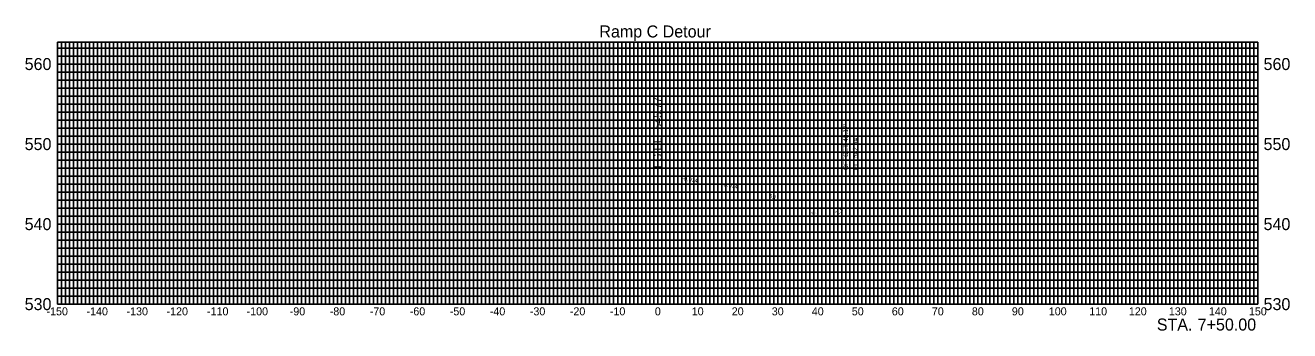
# Model space of a CAD drawing. Extents: x -158 to 158, y 523 to 600.
import ezdxf

# ---------------------------------------------------------------- set-up
doc = ezdxf.new("R2010")
doc.units = 0
for name, color, linetype in [('DES - SHEET - Light Grid', 7, 'Continuous'), ('DES - SHEET - Linework', 7, 'Continuous'), ('DES - XS - Proposed - Finished Grade Slopes Text', 7, 'Continuous'), ('DES - XS - Proposed - Text', 7, 'Continuous')]:
    doc.layers.add(name, color=color, linetype=linetype)

msp = doc.modelspace()

# ---------------------------------------------------------------- linework, layer by layer
at = {"layer": 'DES - SHEET - Light Grid'}
for p, q in [((-149, 530), (-149, 595.44)), ((-148, 530), (-148, 595.44)), ((-147, 530), (-147, 595.44)), ((-146, 530), (-146, 595.44)), ((-145, 530), (-145, 595.44)), ((-144, 530), (-144, 595.44)), ((-143, 530), (-143, 595.44)), ((-142, 530), (-142, 595.44)), ((-141, 530), (-141, 595.44)), ((-139, 530), (-139, 595.44)), ((-138, 530), (-138, 595.44)), ((-137, 530), (-137, 595.44)), ((-136, 530), (-136, 595.44)), ((-135, 530), (-135, 595.44)), ((-134, 530), (-134, 595.44)), ((-133, 530), (-133, 595.44)), ((-132, 530), (-132, 595.44)), ((-131, 530), (-131, 595.44)), ((-129, 530), (-129, 595.44)), ((-128, 530), (-128, 595.44)), ((-127, 530), (-127, 595.44)), ((-126, 530), (-126, 595.44)), ((-125, 530), (-125, 595.44)), ((-124, 530), (-124, 595.44)), ((-123, 530), (-123, 595.44)), ((-122, 530), (-122, 595.44)), ((-121, 530), (-121, 595.44)), ((-119, 530), (-119, 595.44)), ((-118, 530), (-118, 595.44)), ((-117, 530), (-117, 595.44)), ((-116, 530), (-116, 595.44)), ((-115, 530), (-115, 595.44)), ((-114, 530), (-114, 595.44)), ((-113, 530), (-113, 595.44)), ((-112, 530), (-112, 595.44)), ((-111, 530), (-111, 595.44)), ((-109, 530), (-109, 595.44)), ((-108, 530), (-108, 595.44)), ((-107, 530), (-107, 595.44)), ((-106, 530), (-106, 595.44)), ((-105, 530), (-105, 595.44)), ((-104, 530), (-104, 595.44)), ((-103, 530), (-103, 595.44)), ((-102, 530), (-102, 595.44)), ((-101, 530), (-101, 595.44)), ((-99, 530), (-99, 595.44)), ((-98, 530), (-98, 595.44)), ((-97, 530), (-97, 595.44)), ((-96, 530), (-96, 595.44)), ((-95, 530), (-95, 595.44)), ((-94, 530), (-94, 595.44)), ((-93, 530), (-93, 595.44)), ((-92, 530), (-92, 595.44)), ((-91, 530), (-91, 595.44)), ((-89, 530), (-89, 595.44)), ((-88, 530), (-88, 595.44)), ((-87, 530), (-87, 595.44)), ((-86, 530), (-86, 595.44)), ((-85, 530), (-85, 595.44)), ((-84, 530), (-84, 595.44)), ((-83, 530), (-83, 595.44)), ((-82, 530), (-82, 595.44)), ((-81, 530), (-81, 595.44)), ((-79, 530), (-79, 595.44)), ((-78, 530), (-78, 595.44)), ((-77, 530), (-77, 595.44)), ((-76, 530), (-76, 595.44)), ((-75, 530), (-75, 595.44)), ((-74, 530), (-74, 595.44)), ((-73, 530), (-73, 595.44)), ((-72, 530), (-72, 595.44)), ((-71, 530), (-71, 595.44)), ((-69, 530), (-69, 595.44)), ((-68, 530), (-68, 595.44)), ((-67, 530), (-67, 595.44)), ((-66, 530), (-66, 595.44)), ((-65, 530), (-65, 595.44)), ((-64, 530), (-64, 595.44)), ((-63, 530), (-63, 595.44)), ((-62, 530), (-62, 595.44)), ((-61, 530), (-61, 595.44)), ((-59, 530), (-59, 595.44)), ((-58, 530), (-58, 595.44)), ((-57, 530), (-57, 595.44)), ((-56, 530), (-56, 595.44)), ((-55, 530), (-55, 595.44)), ((-54, 530), (-54, 595.44)), ((-53, 530), (-53, 595.44)), ((-52, 530), (-52, 595.44)), ((-51, 530), (-51, 595.44)), ((-49, 530), (-49, 595.44)), ((-48, 530), (-48, 595.44)), ((-47, 530), (-47, 595.44)), ((-46, 530), (-46, 595.44)), ((-45, 530), (-45, 595.44)), ((-44, 530), (-44, 595.44)), ((-43, 530), (-43, 595.44)), ((-42, 530), (-42, 595.44)), ((-41, 530), (-41, 595.44)), ((-39, 530), (-39, 595.44)), ((-38, 530), (-38, 595.44)), ((-37, 530), (-37, 595.44)), ((-36, 530), (-36, 595.44)), ((-35, 530), (-35, 595.44)), ((-34, 530), (-34, 595.44)), ((-33, 530), (-33, 595.44)), ((-32, 530), (-32, 595.44)), ((-31, 530), (-31, 595.44)), ((-29, 530), (-29, 595.44)), ((-28, 530), (-28, 595.44)), ((-27, 530), (-27, 595.44)), ((-26, 530), (-26, 595.44)), ((-25, 530), (-25, 595.44)), ((-24, 530), (-24, 595.44)), ((-23, 530), (-23, 595.44)), ((-22, 530), (-22, 595.44)), ((-21, 530), (-21, 595.44)), ((-19, 530), (-19, 595.44)), ((-18, 530), (-18, 595.44)), ((-17, 530), (-17, 595.44)), ((-16, 530), (-16, 595.44)), ((-15, 530), (-15, 595.44)), ((-14, 530), (-14, 595.44)), ((-13, 530), (-13, 595.44)), ((-12, 530), (-12, 595.44)), ((-11, 530), (-11, 595.44)), ((-9, 530), (-9, 595.44)), ((-8, 530), (-8, 595.44)), ((-7, 530), (-7, 595.44)), ((-6, 530), (-6, 595.44)), ((-5, 530), (-5, 595.44)), ((-4, 530), (-4, 595.44)), ((-3, 530), (-3, 595.44)), ((-2, 530), (-2, 595.44)), ((-1, 530), (-1, 595.44)), ((1, 530), (1, 595.44)), ((2, 530), (2, 595.44)), ((3, 530), (3, 595.44)), ((4, 530), (4, 595.44)), ((5, 530), (5, 595.44)), ((6, 530), (6, 595.44)), ((7, 530), (7, 595.44)), ((8, 530), (8, 595.44)), ((9, 530), (9, 595.44)), ((11, 530), (11, 595.44)), ((12, 530), (12, 595.44)), ((13, 530), (13, 595.44)), ((14, 530), (14, 595.44)), ((15, 530), (15, 595.44)), ((16, 530), (16, 595.44)), ((17, 530), (17, 595.44)), ((18, 530), (18, 595.44)), ((19, 530), (19, 595.44)), ((21, 530), (21, 595.44)), ((22, 530), (22, 595.44)), ((23, 530), (23, 595.44)), ((24, 530), (24, 595.44)), ((25, 530), (25, 595.44)), ((26, 530), (26, 595.44)), ((27, 530), (27, 595.44)), ((28, 530), (28, 595.44)), ((29, 530), (29, 595.44)), ((31, 530), (31, 595.44)), ((32, 530), (32, 595.44)), ((33, 530), (33, 595.44)), ((34, 530), (34, 595.44)), ((35, 530), (35, 595.44)), ((36, 530), (36, 595.44)), ((37, 530), (37, 595.44)), ((38, 530), (38, 595.44)), ((39, 530), (39, 595.44)), ((41, 530), (41, 595.44)), ((42, 530), (42, 595.44)), ((43, 530), (43, 595.44)), ((44, 530), (44, 595.44)), ((45, 530), (45, 595.44)), ((46, 530), (46, 595.44)), ((47, 530), (47, 595.44)), ((48, 530), (48, 595.44)), ((49, 530), (49, 595.44)), ((51, 530), (51, 595.44)), ((52, 530), (52, 595.44)), ((53, 530), (53, 595.44)), ((54, 530), (54, 595.44)), ((55, 530), (55, 595.44)), ((56, 530), (56, 595.44)), ((57, 530), (57, 595.44)), ((58, 530), (58, 595.44)), ((59, 530), (59, 595.44)), ((61, 530), (61, 595.44)), ((62, 530), (62, 595.44)), ((63, 530), (63, 595.44)), ((64, 530), (64, 595.44)), ((65, 530), (65, 595.44)), ((66, 530), (66, 595.44)), ((67, 530), (67, 595.44)), ((68, 530), (68, 595.44)), ((69, 530), (69, 595.44)), ((71, 530), (71, 595.44)), ((72, 530), (72, 595.44)), ((73, 530), (73, 595.44)), ((74, 530), (74, 595.44)), ((75, 530), (75, 595.44)), ((76, 530), (76, 595.44)), ((77, 530), (77, 595.44)), ((78, 530), (78, 595.44)), ((79, 530), (79, 595.44)), ((81, 530), (81, 595.44)), ((82, 530), (82, 595.44)), ((83, 530), (83, 595.44)), ((84, 530), (84, 595.44)), ((85, 530), (85, 595.44)), ((86, 530), (86, 595.44)), ((87, 530), (87, 595.44)), ((88, 530), (88, 595.44)), ((89, 530), (89, 595.44)), ((91, 530), (91, 595.44)), ((92, 530), (92, 595.44)), ((93, 530), (93, 595.44)), ((94, 530), (94, 595.44)), ((95, 530), (95, 595.44)), ((96, 530), (96, 595.44)), ((97, 530), (97, 595.44)), ((98, 530), (98, 595.44)), ((99, 530), (99, 595.44)), ((101, 530), (101, 595.44)), ((102, 530), (102, 595.44)), ((103, 530), (103, 595.44)), ((104, 530), (104, 595.44)), ((105, 530), (105, 595.44)), ((106, 530), (106, 595.44)), ((107, 530), (107, 595.44)), ((108, 530), (108, 595.44)), ((109, 530), (109, 595.44)), ((111, 530), (111, 595.44)), ((112, 530), (112, 595.44)), ((113, 530), (113, 595.44)), ((114, 530), (114, 595.44)), ((115, 530), (115, 595.44)), ((116, 530), (116, 595.44)), ((117, 530), (117, 595.44)), ((118, 530), (118, 595.44)), ((119, 530), (119, 595.44)), ((121, 530), (121, 595.44)), ((122, 530), (122, 595.44)), ((123, 530), (123, 595.44)), ((124, 530), (124, 595.44)), ((125, 530), (125, 595.44)), ((126, 530), (126, 595.44)), ((127, 530), (127, 595.44)), ((128, 530), (128, 595.44)), ((129, 530), (129, 595.44)), ((131, 530), (131, 595.44)), ((132, 530), (132, 595.44)), ((133, 530), (133, 595.44)), ((134, 530), (134, 595.44)), ((135, 530), (135, 595.44)), ((136, 530), (136, 595.44)), ((137, 530), (137, 595.44)), ((138, 530), (138, 595.44)), ((139, 530), (139, 595.44)), ((141, 530), (141, 595.44)), ((142, 530), (142, 595.44)), ((143, 530), (143, 595.44)), ((144, 530), (144, 595.44)), ((145, 530), (145, 595.44)), ((146, 530), (146, 595.44)), ((147, 530), (147, 595.44)), ((148, 530), (148, 595.44)), ((149, 530), (149, 595.44)), ((-150, 594), (150, 594)), ((-150, 592), (150, 592)), ((-150, 588), (150, 588)), ((-150, 586), (150, 586)), ((-150, 584), (150, 584)), ((-150, 582), (150, 582)), ((-150, 580), (150, 580)), ((-150, 578), (150, 578)), ((-150, 576), (150, 576)), ((-150, 574), (150, 574)), ((-150, 572), (150, 572)), ((-150, 568), (150, 568)), ((-150, 566), (150, 566)), ((-150, 564), (150, 564)), ((-150, 562), (150, 562)), ((-150, 560), (150, 560)), ((-150, 558), (150, 558)), ((-150, 556), (150, 556)), ((-150, 554), (150, 554)), ((-150, 552), (150, 552)), ((-150, 548), (150, 548)), ((-150, 546), (150, 546)), ((-150, 544), (150, 544)), ((-150, 542), (150, 542)), ((-150, 540), (150, 540)), ((-150, 538), (150, 538)), ((-150, 536), (150, 536)), ((-150, 534), (150, 534)), ((-150, 532), (150, 532))]:
    msp.add_line(p, q, dxfattribs=at)
at = {"layer": 'DES - SHEET - Linework'}
for p, q in [((-150, 595.44), (150, 595.44)), ((-150, 530), (-150, 595.44)), ((-140, 530), (-140, 595.44)), ((-130, 530), (-130, 595.44)), ((-120, 530), (-120, 595.44)), ((-110, 530), (-110, 595.44)), ((-100, 530), (-100, 595.44)), ((-90, 530), (-90, 595.44)), ((-80, 530), (-80, 595.44)), ((-70, 530), (-70, 595.44)), ((-60, 530), (-60, 595.44)), ((-50, 530), (-50, 595.44)), ((-40, 530), (-40, 595.44)), ((-30, 530), (-30, 595.44)), ((-20, 530), (-20, 595.44)), ((-10, 530), (-10, 595.44)), ((0, 530), (0, 595.44)), ((10, 530), (10, 595.44)), ((20, 530), (20, 595.44)), ((30, 530), (30, 595.44)), ((40, 530), (40, 595.44)), ((50, 530), (50, 595.44)), ((60, 530), (60, 595.44)), ((70, 530), (70, 595.44)), ((80, 530), (80, 595.44)), ((90, 530), (90, 595.44)), ((100, 530), (100, 595.44)), ((110, 530), (110, 595.44)), ((120, 530), (120, 595.44)), ((130, 530), (130, 595.44)), ((140, 530), (140, 595.44)), ((150, 530), (150, 595.44)), ((-150, 590), (150, 590)), ((-150, 570), (150, 570)), ((-150, 550), (150, 550)), ((-150, 530), (150, 530))]:
    msp.add_line(p, q, dxfattribs=at)

# ---------------------------------------------------------------- texts
at = {"layer": 'DES - XS - Proposed - Finished Grade Slopes Text'}
for s, height, rotation, p in [("48.17'", 1.2, 90, (47.57, 570.53)), ('OFFSET ', 1.2, 90, (47.57, 563.48)), ('542.54', 1.2, 90, (49.97, 566.46)), ('EL. ', 1.2, 90, (49.97, 563.48)), ('-0.074', 1, 351.5364, (6.08, 560.94)), ('-0.074', 1, 351.5364, (16.08, 559.45)), ('6:1', 1, 341.5651, (27.71, 556.66)), ('4:1', 1, 333.4349, (38.26, 552.6)), ('2:1', 1, 45, (45, 552.21))]:
    msp.add_text(s, height=height, rotation=rotation, dxfattribs=at).set_placement(p)
at = {"layer": 'DES - XS - Proposed - Text'}
for s, height, p in [('Ramp C Detour', 3, (-14.58, 596.64)), ('560', 3, (-158.19, 588.5)), ('560', 3, (151.41, 588.5)), ('550', 3, (-158.19, 568.5)), ('550', 3, (151.41, 568.5)), ('540', 3, (-158.19, 548.5)), ('540', 3, (151.41, 548.5)), ('530', 3, (-158.19, 528.5)), ('530', 3, (151.41, 528.5)), ('-150', 2, (-152.73, 527.2)), ('-140', 2, (-142.73, 527.2)), ('-130', 2, (-132.73, 527.2)), ('-120', 2, (-122.73, 527.2)), ('-110', 2, (-112.62, 527.2)), ('-100', 2, (-102.73, 527.2)), ('-90', 2, (-91.95, 527.2)), ('-80', 2, (-81.95, 527.2)), ('-70', 2, (-71.95, 527.2)), ('-60', 2, (-61.95, 527.2)), ('-50', 2, (-51.95, 527.2)), ('-40', 2, (-41.95, 527.2)), ('-30', 2, (-31.95, 527.2)), ('-20', 2, (-21.95, 527.2)), ('-10', 2, (-11.95, 527.2)), ('0', 2, (-0.71, 527.2)), ('10', 2, (8.51, 527.2)), ('20', 2, (18.51, 527.2)), ('30', 2, (28.51, 527.2)), ('40', 2, (38.51, 527.2)), ('50', 2, (48.51, 527.2)), ('60', 2, (58.51, 527.2)), ('70', 2, (68.51, 527.2)), ('80', 2, (78.51, 527.2)), ('90', 2, (88.51, 527.2)), ('100', 2, (97.74, 527.2)), ('110', 2, (107.84, 527.2)), ('120', 2, (117.74, 527.2)), ('130', 2, (127.74, 527.2)), ('140', 2, (137.74, 527.2)), ('150', 2, (147.74, 527.2)), (' STA. ', 3, (123.61, 523.4)), ('7+50.00', 3, (134.94, 523.4))]:
    msp.add_text(s, height=height, dxfattribs=at).set_placement(p)
for s, p in [("545.77'", (1, 573.57)), ('FG EL. ', (1, 563.94))]:
    msp.add_text(s, height=2, rotation=90, dxfattribs=at).set_placement(p)

doc.saveas('drawing.dxf')
